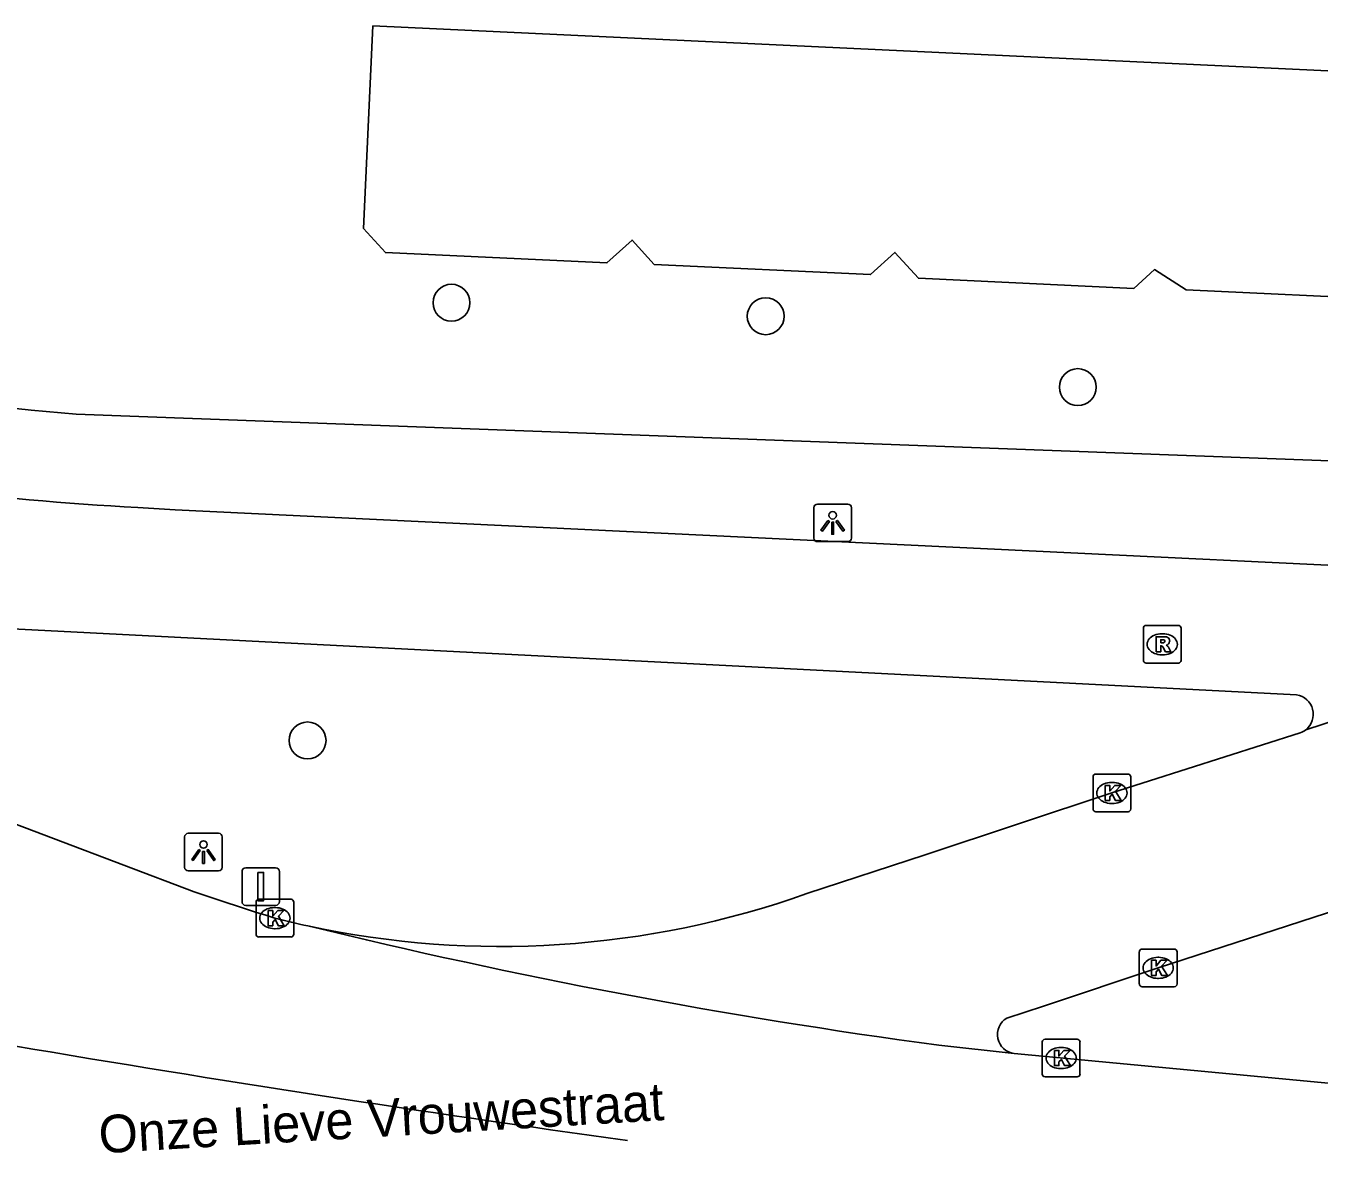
# Model space of a CAD drawing. Extents: x 161253 to 161848, y 384872 to 385383.
# Drawn here: x 161391.36 to 161425.66, y 384883.88 to 384913.79 of the extents above; entities that cross this region are included whole.
import ezdxf

# ---------------------------------------------------------------- set-up
doc = ezdxf.new("R2010")
doc.units = 0
for name, color, linetype in [('IMGEO_Boom', 7, 'Continuous'), ('IMGEO_Fietspad_gesloten', 7, 'Continuous'), ('IMGEO_Kolk', 7, 'Continuous'), ('IMGEO_Lichtpunt', 7, 'Continuous'), ('IMGEO_Openbare_ruimte_label', 7, 'Continuous'), ('IMGEO_Pand', 7, 'Continuous'), ('IMGEO_Rijbaan_lokaal_open', 7, 'Continuous'), ('IMGEO_Rijbaan_regionaal_gesloten', 7, 'Continuous'), ('IMGEO_Rioolput', 7, 'Continuous'), ('IMGEO_Verkeersbordpaal', 7, 'Continuous'), ('IMGEO_Voetpad_open', 7, 'Continuous')]:
    doc.layers.add(name, color=color, linetype=linetype)

msp = doc.modelspace()

# ---------------------------------------------------------------- linework, layer by layer
at = {"layer": 'IMGEO_Boom'}
for centre in [(161402.645, 384906.447), (161410.979, 384906.088), (161419.258, 384904.209), (161398.828, 384894.835)]:
    msp.add_circle(centre, 0.489, dxfattribs=at)
at = {"layer": 'IMGEO_Fietspad_gesloten'}
for points in [[(161394.326, 384901.014), (161395.318, 384900.953), (161432.148, 384899.181)], [(161385.143, 384898.097), (161425.059, 384896.042)]]:
    msp.add_lwpolyline(points, dxfattribs=at)
for centre, radius, start, end in [((161398.556, 384980.656), 79.754, 262.8094, 266.95981), ((161424.983, 384895.526), 0.521, 308.0291, 81.6103)]:
    msp.add_arc(centre, radius, start, end, dxfattribs=at)
at = {"layer": 'IMGEO_Kolk'}
for p, q in [((161419.663, 384893.015), (161419.663, 384893.867)), ((161419.738, 384893.941), (161420.59, 384893.941)), ((161420.151, 384893.721), (161420.176, 384893.721)), ((161420.664, 384893.867), (161420.664, 384893.015)), ((161420.59, 384892.941), (161419.738, 384892.941)), ((161420.174, 384893.161), (161420.149, 384893.161)), ((161397.461, 384889.693), (161397.461, 384890.545)), ((161397.536, 384890.619), (161398.388, 384890.619)), ((161398.462, 384890.545), (161398.462, 384889.693)), ((161397.949, 384890.399), (161397.974, 384890.399)), ((161398.388, 384889.619), (161397.536, 384889.619)), ((161397.972, 384889.839), (161397.947, 384889.839)), ((161420.89, 384888.374), (161420.89, 384889.226)), ((161420.965, 384889.3), (161421.817, 384889.3)), ((161421.891, 384889.226), (161421.891, 384888.374)), ((161421.378, 384889.08), (161421.403, 384889.08)), ((161421.401, 384888.52), (161421.376, 384888.52)), ((161421.817, 384888.3), (161420.965, 384888.3)), ((161418.315, 384885.982), (161418.315, 384886.834)), ((161418.39, 384886.908), (161419.242, 384886.908)), ((161419.316, 384886.834), (161419.316, 384885.982)), ((161418.803, 384886.688), (161418.828, 384886.688)), ((161418.826, 384886.128), (161418.801, 384886.128)), ((161419.242, 384885.908), (161418.39, 384885.908))]:
    msp.add_line(p, q, dxfattribs=at)
for points in [[(161419.663, 384893.015), (161419.663, 384893.867)], [(161419.738, 384893.941), (161420.59, 384893.941)], [(161419.984, 384893.641), (161420.107, 384893.641), (161420.107, 384893.49), (161420.237, 384893.641), (161420.401, 384893.641), (161420.255, 384893.49), (161420.408, 384893.241), (161420.256, 384893.241), (161420.171, 384893.405), (161420.107, 384893.338), (161420.107, 384893.241), (161419.984, 384893.241), (161419.984, 384893.641)], [(161420.664, 384893.867), (161420.664, 384893.015)], [(161420.59, 384892.941), (161419.738, 384892.941)], [(161397.461, 384889.693), (161397.461, 384890.545)], [(161397.536, 384890.619), (161398.388, 384890.619)], [(161398.462, 384890.545), (161398.462, 384889.693)], [(161397.782, 384890.319), (161397.905, 384890.319), (161397.905, 384890.168), (161398.035, 384890.319), (161398.199, 384890.319), (161398.053, 384890.168), (161398.206, 384889.919), (161398.054, 384889.919), (161397.969, 384890.083), (161397.905, 384890.016), (161397.905, 384889.919), (161397.782, 384889.919), (161397.782, 384890.319)], [(161398.388, 384889.619), (161397.536, 384889.619)], [(161420.89, 384888.374), (161420.89, 384889.226)], [(161420.965, 384889.3), (161421.817, 384889.3)], [(161421.891, 384889.226), (161421.891, 384888.374)], [(161421.211, 384889), (161421.334, 384889), (161421.334, 384888.849), (161421.464, 384889), (161421.628, 384889), (161421.482, 384888.849), (161421.635, 384888.6), (161421.483, 384888.6), (161421.398, 384888.764), (161421.334, 384888.697), (161421.334, 384888.6), (161421.211, 384888.6), (161421.211, 384889)], [(161421.817, 384888.3), (161420.965, 384888.3)], [(161418.315, 384885.982), (161418.315, 384886.834)], [(161418.39, 384886.908), (161419.242, 384886.908)], [(161419.316, 384886.834), (161419.316, 384885.982)], [(161418.636, 384886.608), (161418.759, 384886.608), (161418.759, 384886.457), (161418.889, 384886.608), (161419.053, 384886.608), (161418.907, 384886.457), (161419.06, 384886.208), (161418.908, 384886.208), (161418.823, 384886.372), (161418.759, 384886.305), (161418.759, 384886.208), (161418.636, 384886.208), (161418.636, 384886.608)], [(161419.242, 384885.908), (161418.39, 384885.908)]]:
    msp.add_lwpolyline(points, dxfattribs=at)
for centre, start, end in [((161419.74, 384893.865), 91.552, 178.448), ((161419.74, 384893.865), 91.552, 178.448), ((161420.588, 384893.865), 1.552, 88.448), ((161420.588, 384893.865), 1.552, 88.448), ((161419.74, 384893.017), 181.552, 268.448), ((161419.74, 384893.017), 181.552, 268.448), ((161420.588, 384893.017), 271.552, 358.448), ((161420.588, 384893.017), 271.552, 358.448), ((161397.538, 384890.543), 91.552, 178.448), ((161397.538, 384890.543), 91.552, 178.448), ((161398.386, 384890.543), 1.552, 88.448), ((161398.386, 384890.543), 1.552, 88.448), ((161397.538, 384889.695), 181.552, 268.448), ((161397.538, 384889.695), 181.552, 268.448), ((161398.386, 384889.695), 271.552, 358.448), ((161398.386, 384889.695), 271.552, 358.448), ((161420.967, 384889.224), 91.552, 178.448), ((161420.967, 384889.224), 91.552, 178.448), ((161421.815, 384889.224), 1.552, 88.448), ((161421.815, 384889.224), 1.552, 88.448), ((161420.967, 384888.376), 181.552, 268.448), ((161420.967, 384888.376), 181.552, 268.448), ((161421.815, 384888.376), 271.552, 358.448), ((161421.815, 384888.376), 271.552, 358.448), ((161418.392, 384886.832), 91.552, 178.448), ((161418.392, 384886.832), 91.552, 178.448), ((161419.24, 384886.832), 1.552, 88.448), ((161419.24, 384886.832), 1.552, 88.448), ((161418.392, 384885.984), 181.552, 268.448), ((161418.392, 384885.984), 181.552, 268.448), ((161419.24, 384885.984), 271.552, 358.448), ((161419.24, 384885.984), 271.552, 358.448)]:
    msp.add_arc(centre, 0.0765, start, end, dxfattribs=at)
for centre, major_axis, ratio, start_param, end_param in [((161420.15, 384893.441), (-0.387, 0.002), 0.722429, 4.712389, 7.853982), ((161420.175, 384893.441), (-0.39, 0.002), 0.717154, 1.570796, 4.712389), ((161397.948, 384890.119), (-0.387, 0.002), 0.722429, 4.712389, 7.853982), ((161397.973, 384890.119), (-0.39, 0.002), 0.717154, 1.570796, 4.712389), ((161421.377, 384888.8), (-0.387, 0.002), 0.722429, 4.712389, 7.853982), ((161421.402, 384888.8), (-0.39, 0.002), 0.717154, 1.570796, 4.712389), ((161418.802, 384886.408), (-0.387, 0.002), 0.722429, 4.712389, 7.853982), ((161418.827, 384886.408), (-0.39, 0.002), 0.717154, 1.570796, 4.712389)]:
    msp.add_ellipse(centre, major_axis=major_axis, ratio=ratio, start_param=start_param, end_param=end_param, dxfattribs=at)
at = {"layer": 'IMGEO_Lichtpunt'}
for p, q in [((161412.257, 384901.009), (161412.257, 384900.202)), ((161412.257, 384901.009), (161412.257, 384900.202)), ((161413.159, 384901.104), (161412.351, 384901.104)), ((161413.159, 384901.104), (161412.351, 384901.104)), ((161413.253, 384900.202), (161413.253, 384901.009)), ((161413.253, 384900.202), (161413.253, 384901.009)), ((161412.351, 384900.108), (161413.159, 384900.108)), ((161412.351, 384900.108), (161413.159, 384900.108)), ((161395.567, 384892.275), (161395.567, 384891.468)), ((161395.567, 384892.275), (161395.567, 384891.468)), ((161396.469, 384892.37), (161395.661, 384892.37)), ((161396.469, 384892.37), (161395.661, 384892.37)), ((161396.563, 384891.468), (161396.563, 384892.275)), ((161396.563, 384891.468), (161396.563, 384892.275)), ((161395.661, 384891.374), (161396.469, 384891.374)), ((161395.661, 384891.374), (161396.469, 384891.374))]:
    msp.add_line(p, q, dxfattribs=at)
for points in [[(161412.631, 384900.673), (161412.67, 384900.645), (161412.482, 384900.383), (161412.444, 384900.41), (161412.631, 384900.673)], [(161412.733, 384900.625), (161412.78, 384900.625), (161412.78, 384900.303), (161412.733, 384900.303), (161412.733, 384900.625)], [(161412.843, 384900.645), (161412.881, 384900.672), (161413.068, 384900.41), (161413.029, 384900.382), (161412.843, 384900.645)], [(161395.941, 384891.939), (161395.98, 384891.911), (161395.792, 384891.649), (161395.754, 384891.676), (161395.941, 384891.939)], [(161396.153, 384891.911), (161396.191, 384891.938), (161396.378, 384891.676), (161396.339, 384891.648), (161396.153, 384891.911)], [(161396.043, 384891.891), (161396.09, 384891.891), (161396.09, 384891.569), (161396.043, 384891.569), (161396.043, 384891.891)]]:
    msp.add_lwpolyline(points, dxfattribs=at)
for centre in [(161412.756, 384900.807), (161396.066, 384892.073)]:
    msp.add_circle(centre, 0.0994, dxfattribs=at)
for centre, start, end in [((161412.351, 384901.009), 90, 180), ((161412.351, 384901.009), 90, 180), ((161413.159, 384901.009), 0, 90), ((161413.159, 384901.009), 0, 90), ((161412.351, 384900.202), 180, 270), ((161412.351, 384900.202), 180, 270), ((161413.159, 384900.202), 270, 0), ((161413.159, 384900.202), 270, 360), ((161395.661, 384892.275), 90, 180), ((161395.661, 384892.275), 90, 180), ((161396.469, 384892.275), 0, 90), ((161396.469, 384892.275), 0, 90), ((161395.661, 384891.468), 180, 270), ((161395.661, 384891.468), 180, 270), ((161396.469, 384891.468), 270, 0), ((161396.469, 384891.468), 270, 360)]:
    msp.add_arc(centre, 0.0946, start, end, dxfattribs=at)
at = {"layer": 'IMGEO_Pand'}
msp.add_lwpolyline([(161430.768, 384912.367), (161435.762, 384912.131), (161435.505, 384906.68), (161434.889, 384906.119), (161428.885, 384906.402), (161428.321, 384907.022), (161427.768, 384906.519), (161422.131, 384906.785), (161421.289, 384907.325), (161420.743, 384906.828), (161415.03, 384907.098), (161414.408, 384907.782), (161413.761, 384907.193), (161408.021, 384907.464), (161407.435, 384908.109), (161406.767, 384907.501), (161400.891, 384907.778), (161400.31, 384908.417), (161400.545, 384913.412), (161400.563, 384913.792), (161430.768, 384912.367)], dxfattribs=at)
at = {"layer": 'IMGEO_Rijbaan_lokaal_open'}
for points in [[(161432.148, 384899.181), (161432.042, 384897.321), (161425.304, 384895.116)], [(161425.158, 384895.035), (161420.164, 384893.441), (161415.208, 384891.797), (161412.072, 384890.772)], [(161427.57, 384890.811), (161421.391, 384888.8), (161418.346, 384887.783), (161417.374, 384887.467)]]:
    msp.add_lwpolyline(points, dxfattribs=at)
for centre, radius, start, end in [((161424.996, 384895.499), 0.492, 289.245, 308.7976), ((161403.947, 384913.55), 24.183, 257.7953, 289.6306), ((161417.636, 384887.031), 0.509, 120.9475, 262.8176)]:
    msp.add_arc(centre, radius, start, end, dxfattribs=at)
at = {"layer": 'IMGEO_Rijbaan_regionaal_gesloten'}
for points in [[(161395.816, 384890.82), (161390.211, 384892.939)], [(161417.572, 384886.526), (161415.575, 384886.745)], [(161433.661, 384885.003), (161433.198, 384885.047), (161417.572, 384886.526)]]:
    msp.add_lwpolyline(points, dxfattribs=at)
for centre, radius, start, end in [((161418.628, 384957.021), 70.021, 250.98646, 252.83384), ((161404.161, 384914.436), 25.095, 255.6989, 257.7469), ((161437.172, 385046.676), 161.382, 256.2579, 262.30943), ((161485.028, 385441.523), 562.698, 260.38423, 262.06157)]:
    msp.add_arc(centre, radius, start, end, dxfattribs=at)
at = {"layer": 'IMGEO_Rioolput'}
for p, q in [((161420.998, 384896.959), (161420.998, 384897.811)), ((161421.073, 384897.885), (161421.925, 384897.885)), ((161421.999, 384897.811), (161421.999, 384896.959)), ((161421.486, 384897.665), (161421.511, 384897.665)), ((161421.509, 384897.105), (161421.484, 384897.105)), ((161421.925, 384896.885), (161421.073, 384896.885))]:
    msp.add_line(p, q, dxfattribs=at)
for points in [[(161420.998, 384896.959), (161420.998, 384897.811)], [(161421.073, 384897.885), (161421.925, 384897.885)], [(161421.999, 384897.811), (161421.999, 384896.959)], [(161421.587, 384897.583), (161421.335, 384897.585), (161421.335, 384897.185)], [(161421.513, 384897.504), (161421.459, 384897.504), (161421.459, 384897.423)], [(161421.459, 384897.423), (161421.511, 384897.423)], [(161421.335, 384897.185), (161421.459, 384897.185), (161421.459, 384897.347), (161421.47, 384897.347)], [(161421.517, 384897.318), (161421.588, 384897.185), (161421.728, 384897.185), (161421.663, 384897.311)], [(161421.925, 384896.885), (161421.073, 384896.885)]]:
    msp.add_lwpolyline(points, dxfattribs=at)
for centre, radius, start, end in [((161421.075, 384897.809), 0.0765, 91.552, 178.448), ((161421.075, 384897.809), 0.0765, 91.552, 178.448), ((161421.923, 384897.809), 0.0765, 1.552, 88.448), ((161421.923, 384897.809), 0.0765, 1.552, 88.448), ((161421.495, 384897.612), 0.19, 274.7715, 282.9687), ((161421.519, 384897.408), 0.0964, 77.0061, 93.1865), ((161421.533, 384897.465), 0.0378, 276.6634, 79.6772), ((161421.586, 384897.473), 0.109, 350.3612, 89.416), ((161421.584, 384897.473), 0.112, 277.5842, 350.9817), ((161421.469, 384897.294), 0.0533, 26.0293, 88.6989), ((161421.568, 384897.258), 0.108, 29.5134, 73.7905), ((161421.075, 384896.961), 0.0765, 181.552, 268.448), ((161421.075, 384896.961), 0.0765, 181.552, 268.448), ((161421.923, 384896.961), 0.0765, 271.552, 358.448), ((161421.923, 384896.961), 0.0765, 271.552, 358.448)]:
    msp.add_arc(centre, radius, start, end, dxfattribs=at)
for centre, major_axis, ratio, start_param, end_param in [((161421.485, 384897.385), (-0.387, 0.002), 0.722429, 4.712389, 7.853982), ((161421.51, 384897.385), (-0.39, 0.002), 0.717154, 1.570796, 4.712389)]:
    msp.add_ellipse(centre, major_axis=major_axis, ratio=ratio, start_param=start_param, end_param=end_param, dxfattribs=at)
at = {"layer": 'IMGEO_Verkeersbordpaal'}
for p, q in [((161397.089, 384890.557), (161397.089, 384891.357)), ((161397.089, 384891.357), (161397.089, 384890.557)), ((161397.189, 384891.457), (161397.979, 384891.457)), ((161397.979, 384891.457), (161397.189, 384891.457)), ((161398.079, 384891.357), (161398.079, 384890.557)), ((161398.079, 384890.557), (161398.079, 384891.357)), ((161397.979, 384890.457), (161397.189, 384890.457)), ((161397.189, 384890.457), (161397.979, 384890.457))]:
    msp.add_line(p, q, dxfattribs=at)
msp.add_lwpolyline([(161397.509, 384891.332), (161397.659, 384891.332), (161397.659, 384890.582), (161397.509, 384890.582), (161397.509, 384891.332)], dxfattribs=at)
for centre, start, end in [((161397.189, 384891.357), 90, 180), ((161397.189, 384891.357), 90, 180), ((161397.979, 384891.357), 0, 90), ((161397.979, 384891.357), 360, 90), ((161397.189, 384890.557), 180, 270), ((161397.189, 384890.557), 180, 270), ((161397.979, 384890.557), 270, 0), ((161397.979, 384890.557), 270, 0)]:
    msp.add_arc(centre, 0.1, start, end, dxfattribs=at)
at = {"layer": 'IMGEO_Voetpad_open'}
msp.add_lwpolyline([(161446.603, 384901.485), (161392.69, 384903.491)], dxfattribs=at)
msp.add_arc((161401.795, 385012.165), 109.054, 258.46978, 265.21062, dxfattribs=at)

# ---------------------------------------------------------------- texts
at = {"layer": 'IMGEO_Openbare_ruimte_label'}
msp.add_text('Onze Lieve Vrouwestraat', height=1, rotation=3.3833, dxfattribs=at).set_placement((161393.315, 384883.877))

doc.saveas('drawing.dxf')
